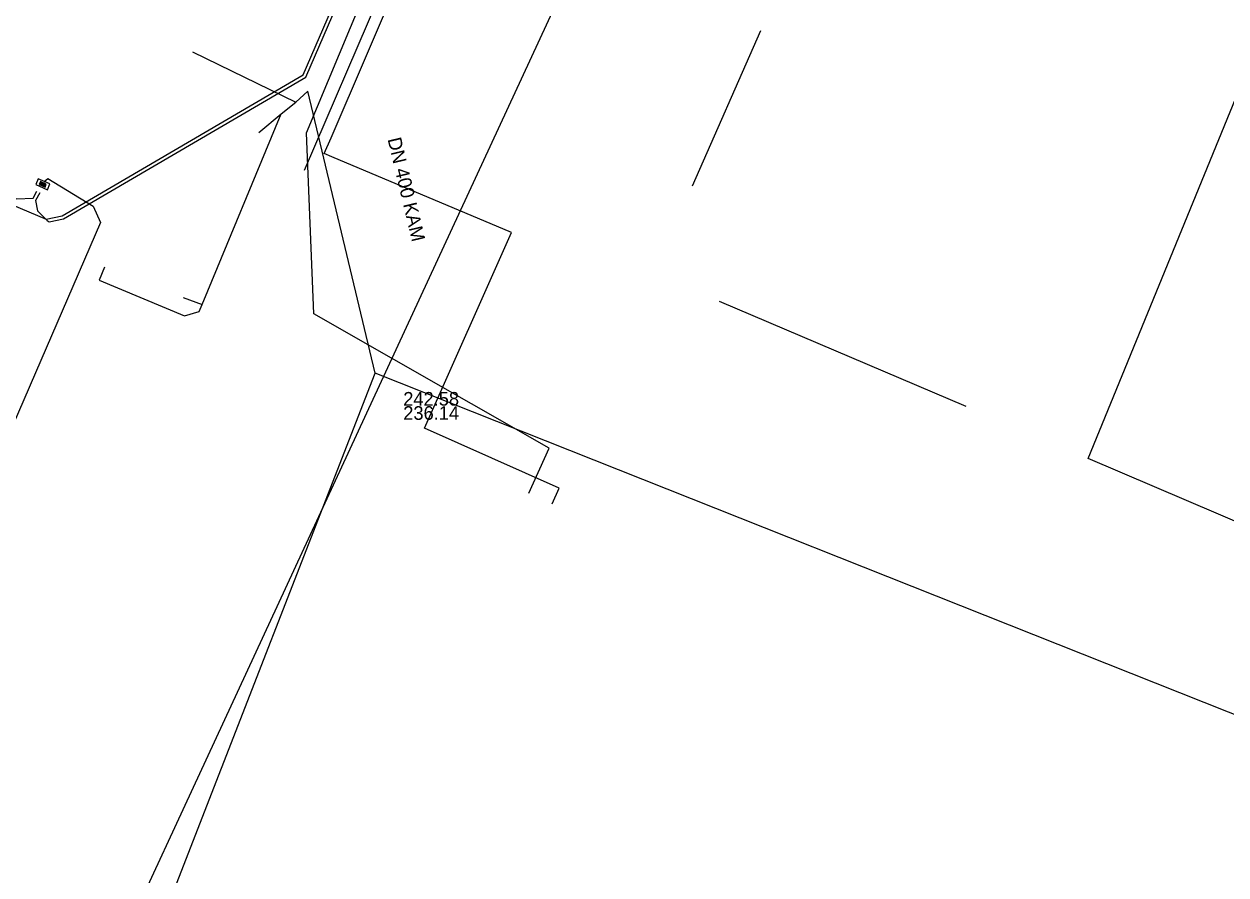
# Model space of a CAD drawing. Extents: x -596024 to -594475, y -1163820 to -1161957.
# Drawn here: x -594616.3 to -594545.9, y -1162353.6 to -1162303.7 of the extents above; entities that cross this region are included whole.
import ezdxf

# ---------------------------------------------------------------- set-up
doc = ezdxf.new("R2010")
doc.units = 0
for name, color, linetype in [('Vrstva 1', 7, 'Continuous'), ('Vrstva 12', 7, 'Continuous'), ('Vrstva 28', 7, 'Continuous'), ('Vrstva 42', 7, 'Continuous'), ('Vrstva 43', 7, 'Continuous'), ('Vrstva 55', 7, 'Continuous'), ('Vrstva 9', 7, 'Continuous')]:
    doc.layers.add(name, color=color, linetype=linetype)

# ---------------------------------------------------------------- blocks, each defined once
blk = doc.blocks.new('NN620')
at = {"layer": 'Vrstva 28'}
for points in [[(0.752, 0.004), (-0.748, 0.004)], [(-0.748, 0.004), (-0.748, -0.746)], [(0.752, -0.746), (0.752, 0.004)], [(-0.748, -0.746), (0.752, -0.746)], [(0.368, -0.18), (-0.376, -0.18)], [(-0.376, -0.18), (-0.376, -0.558)], [(-0.376, -0.558), (0.368, -0.558)], [(0.321, -0.227), (-0.329, -0.227)], [(-0.329, -0.227), (-0.329, -0.51)], [(-0.329, -0.51), (0.321, -0.51)], [(0.274, -0.274), (-0.281, -0.274)], [(-0.281, -0.274), (-0.281, -0.463)], [(-0.281, -0.463), (0.274, -0.463)], [(0.227, -0.321), (-0.234, -0.321)], [(-0.234, -0.321), (-0.234, -0.416)], [(-0.234, -0.416), (0.227, -0.416)], [(-0.193, -0.369), (0.185, -0.369)], [(0.227, -0.416), (0.227, -0.321)], [(0.274, -0.463), (0.274, -0.274)], [(0.321, -0.51), (0.321, -0.227)], [(0.368, -0.558), (0.368, -0.18)]]:
    blk.add_lwpolyline(points, dxfattribs=at)

msp = doc.modelspace()

# ---------------------------------------------------------------- linework, layer by layer
at = {"layer": 'Vrstva 1'}
for p, q in [((-594606.447, -1162305.318), (-594600.395, -1162308.259)), ((-594602.568, -1162310.049), (-594601.247, -1162308.941)), ((-594611.604, -1162317.935), (-594611.912, -1162318.7)), ((-594607.001, -1162319.725), (-594605.892, -1162320.125))]:
    msp.add_line(p, q, dxfattribs=at)
msp.add_lwpolyline([(-594611.912, -1162318.7), (-594606.916, -1162320.79), (-594606.063, -1162320.535), (-594605.892, -1162320.125), (-594601.247, -1162308.941), (-594600.395, -1162308.259), (-594599.683, -1162307.609)], dxfattribs=at)
at = {"layer": 'Vrstva 12'}
for points in [[(-594632.85, -1162405.6), (-594583.38, -1162298.67), (-594575.4, -1162280.72)], [(-594585.37, -1162331.82), (-594584.96, -1162330.9), (-594592.85, -1162327.39), (-594587.74, -1162315.91), (-594598.28, -1162311.47), (-594598.74, -1162311.27), (-594598.33, -1162310.36), (-594587.72, -1162285.63), (-594586.57, -1162282.97), (-594577.37, -1162287.17), (-594575.71, -1162287.91)], [(-594586.74, -1162331.21), (-594585.55, -1162328.56), (-594599.33, -1162320.67), (-594599.76, -1162310.07), (-594590.64, -1162288.18), (-594585.25, -1162287.79)]]:
    msp.add_lwpolyline(points, dxfattribs=at)
at = {"layer": 'Vrstva 42'}
for points in [[(-594615.393, -1162313.572), (-594615.651, -1162314.037), (-594615.54, -1162314.64), (-594614.96, -1162315.2), (-594614.846, -1162315.285), (-594614.013, -1162315.114), (-594599.811, -1162306.79), (-594593.078, -1162291.24), (-594586.962, -1162277.132), (-594585.953, -1162276.59), (-594584.977, -1162276.971), (-594584.528, -1162277.669)], [(-594728.14, -1162370.698), (-594726.956, -1162371.184), (-594717.587, -1162374.854), (-594713.145, -1162376.58), (-594712.358, -1162376.883), (-594702.774, -1162380.887), (-594701.037, -1162381.542), (-594698.579, -1162381.799), (-594695.733, -1162380.998), (-594693.998, -1162379.802), (-594691.846, -1162375.58), (-594680.091, -1162380.768), (-594655.603, -1162390.549), (-594655.097, -1162389.889), (-594640.452, -1162355.111), (-594622.607, -1162312.656), (-594621.792, -1162312.27), (-594615.03, -1162315.126), (-594614.087, -1162314.926), (-594599.969, -1162306.65), (-594593.262, -1162291.16), (-594589.645, -1162282.816), (-594589.61, -1162282.11)], [(-594619.5, -1162312.86), (-594616.74, -1162313.93), (-594615.795, -1162313.885), (-594615.583, -1162313.479)], [(-594615.15, -1162312.91), (-594614.93, -1162312.74), (-594612.28, -1162314.36), (-594611.84, -1162315.32), (-594617.27, -1162327.89)]]:
    msp.add_lwpolyline(points, dxfattribs=at)
at = {"layer": 'Vrstva 55'}
for p, q in [((-594599.89, -1162312.26), (-594585.16, -1162277.99)), ((-594553.95, -1162329.17), (-594540.71, -1162296.82)), ((-594573.154, -1162304.077), (-594577.164, -1162313.19)), ((-594561.094, -1162326.114), (-594575.552, -1162319.959)), ((-594535.429, -1162337.076), (-594553.95, -1162329.17))]:
    msp.add_line(p, q, dxfattribs=at)
at = {"layer": 'Vrstva 9'}
for p, q in [((-594595.735, -1162324.168), (-594599.683, -1162307.609)), ((-594611.666, -1162365.128), (-594595.735, -1162324.168)), ((-594534.435, -1162348.543), (-594595.735, -1162324.168))]:
    msp.add_line(p, q, dxfattribs=at)

# ---------------------------------------------------------------- block references
at = {"layer": 'Vrstva 43', "xscale": 0.5, "yscale": 0.5, "rotation": -23.999999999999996}
msp.add_blockref('NN620', (-594615.15, -1162312.91), dxfattribs=at)

# ---------------------------------------------------------------- texts
at = {"layer": 'Vrstva 12'}
msp.add_text('DN 400 KAM', height=0.8, rotation=283.41012, dxfattribs=at).set_placement((-594595.019, -1162310.43))
for s, p in [('242.58', (-594594.095, -1162326.066)), ('236.14', (-594594.095, -1162326.898))]:
    msp.add_text(s, height=0.8, dxfattribs=at).set_placement(p)

doc.saveas('drawing.dxf')
